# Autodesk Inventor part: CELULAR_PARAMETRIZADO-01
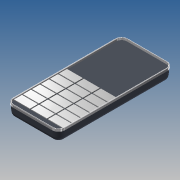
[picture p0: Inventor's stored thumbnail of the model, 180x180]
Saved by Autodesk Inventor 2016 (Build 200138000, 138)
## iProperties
Created: 2011-11
Part Number: CELULAR_PARAMETRIZADO-01
Material: ABS Plastic
Document SubType Name: Modeling
Designer: julian.chica
Mass: 57.5048 g
Surface Area: 199.944 cm^2
Volume: 54.2498 cm^3
Density: 1.06 g/cm^3
Appearance: Plastic (White)
Author: julian.chica
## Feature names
1. Extrusion1
2. desmolde
3. Fillet1
4. Fillet2
5. Sweep1
6. Extrusion2
7. Rectangular Pattern1
## Parameters: ancho = 49.5 mm, d3 = 0, desmolde = -3 deg, redondeo_inferior = 6 mm, d6 = 4.5 mm, d7 = 0, ancho_tecla = 15.27871 mm, d10 = 0.7 mm, d11 = 0, dir1_pattern = 32.55742 mm, dir2_pattern = 8.63935 mm, alto_tecla = 7.63935 mm, d23 = 0.20628 mm, d24 = 1.03707 mm, d29 = 1.52959 mm, d30 = 1.90569 mm, ancho_total_teclado = 47.83613 mm, d32 = 0
